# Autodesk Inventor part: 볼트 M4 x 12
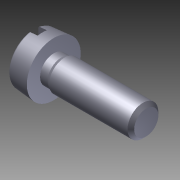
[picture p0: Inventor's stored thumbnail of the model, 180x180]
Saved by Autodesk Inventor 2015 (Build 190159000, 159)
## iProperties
Created: 2025-08
Part Number: 볼트 M4 x 12
Material: 일반
Document SubType Name: Modeling
Designer: USER
Density: 1 g/cm^3
Appearance: 기본값
Author: USER
Author: jhkim
Description: 6각머리 태핑 나사
Creation Date: 2025-08-05
Sending System: Autodesk Inventor 2026
Preprocessor: ST-DEVELOPER v20.1
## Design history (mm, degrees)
node "볼트 M4 x 121"
body "Solid1"
node "기준1"
